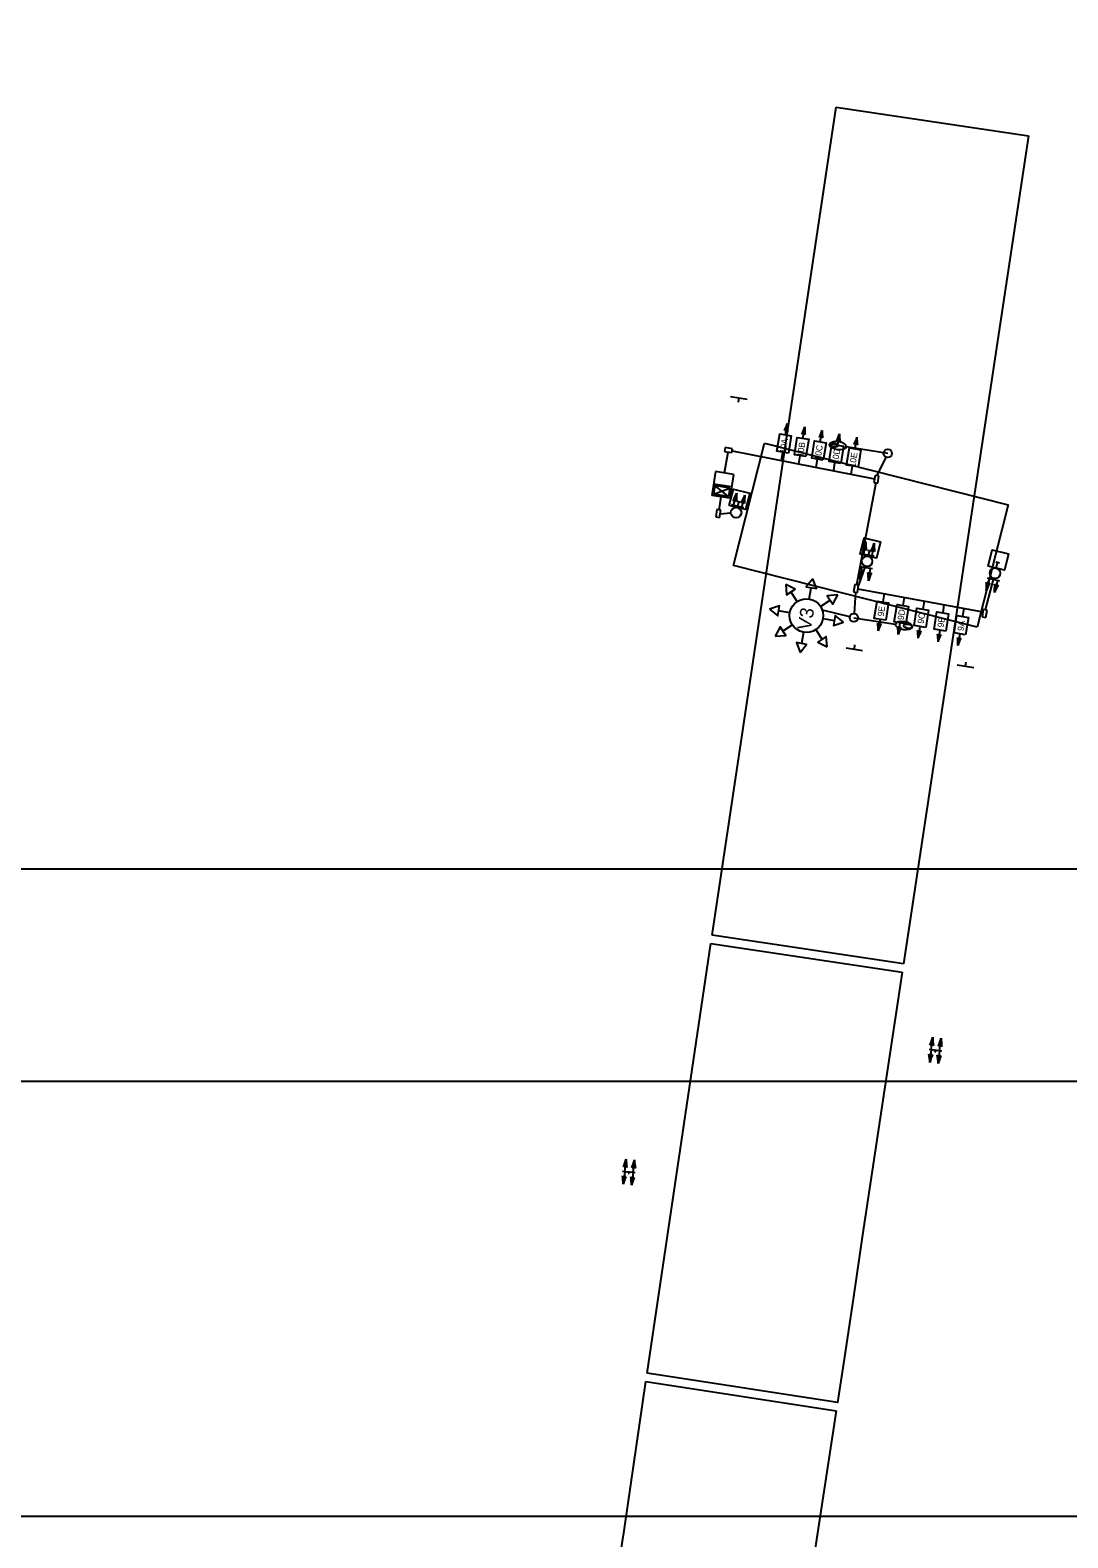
# Model space of a CAD drawing. Extents: x 991933 to 997296, y 1973751 to 1976728.
# Drawn here: x 992879.1 to 993125.8, y 1975643.9 to 1976002.3 of the extents above; entities that cross this region are included whole.
import ezdxf

# ---------------------------------------------------------------- set-up
doc = ezdxf.new("R2010")
doc.units = 0
for name, color, linetype in [('DSN_DRFT_Common-Annotations', 7, 'Continuous'), ('EX_CONTOUR_MINOR', 7, 'Continuous'), ('EX_TERRAIN', 7, 'Continuous'), ('EX_TERRAIN_TRIANGLES', 7, 'Continuous'), ('Level 23', 7, 'Continuous'), ('S_CROSS_DRAIN', 7, 'Continuous'), ('S_CURB', 7, 'Continuous'), ('S_DRIVEWAY', 7, 'Continuous'), ('S_DROP_INLET', 7, 'Continuous'), ('S_PARKING', 7, 'Continuous'), ('S_PAVEMENT_CROWN', 7, 'Continuous'), ('S_SIDEWALK', 7, 'Continuous')]:
    doc.layers.add(name, color=color, linetype=linetype)

msp = doc.modelspace()

# ---------------------------------------------------------------- linework, layer by layer
at = {"layer": 'DSN_DRFT_Common-Annotations'}
for p, q in [((993025.47, 1975681.06), (993070.74, 1975674.09)), ((993070.74, 1975674.09), (993062.63, 1975621.12))]:
    msp.add_line(p, q, dxfattribs=at)
msp.add_lwpolyline([(992995.69, 1975483.29), (992995.69, 1975483.29), (992995.69, 1975483.29), (992996.07, 1975485.68), (992998.13, 1975500.54), (993000.43, 1975515.34), (993002.81, 1975530.17), (993005.1, 1975545.07), (993007.26, 1975559.93), (993009.39, 1975574.75), (993011.66, 1975589.56), (993014.03, 1975604.36), (993015.04, 1975610.86), (993016.22, 1975619.18), (993016.22, 1975619.18), (993016.22, 1975619.18), (993016.22, 1975619.18), (993016.22, 1975619.18), (993020.39, 1975646.15), (993020.39, 1975646.15), (993020.39, 1975646.15), (993025.47, 1975681.06)], dxfattribs=at)
at = {"layer": 'EX_CONTOUR_MINOR'}
for p, q in [((993046.35, 1975875.06), (993053.72, 1975904.14)), ((993053.72, 1975904.14), (993111.64, 1975889.46)), ((993111.64, 1975889.46), (993104.27, 1975860.38)), ((993104.27, 1975860.38), (993046.35, 1975875.06))]:
    msp.add_line(p, q, dxfattribs=at)
at = {"layer": 'EX_TERRAIN'}
for p, q in [((993025.77, 1975683.04), (993040.96, 1975785.2)), ((993040.96, 1975785.2), (993086.44, 1975778.39)), ((993071.04, 1975676.07), (993025.77, 1975683.04))]:
    msp.add_line(p, q, dxfattribs=at)
msp.add_lwpolyline([(993086.44, 1975778.39), (993077.02, 1975715.99), (993074.81, 1975701.23), (993072.59, 1975686.4), (993071.04, 1975676.07), (993071.04, 1975676.07)], dxfattribs=at)
at = {"layer": 'EX_TERRAIN_TRIANGLES'}
for p, q in [((993041.25, 1975787.18), (993070.72, 1975984)), ((993070.72, 1975984), (993116.44, 1975977.15)), ((993116.44, 1975977.15), (993086.74, 1975780.37)), ((993086.74, 1975780.37), (993041.25, 1975787.18))]:
    msp.add_line(p, q, dxfattribs=at)
at = {"layer": 'Level 23'}
for points in [[(992579.43, 1975649.05), (993569.43, 1975649.05), (993569.43, 1976279.05), (992579.43, 1976279.05)], [(992760.73, 1975752.49), (993420.73, 1975752.49), (993420.73, 1976172.49), (992760.73, 1976172.49)], [(992705.67, 1975382.9), (993365.67, 1975382.9), (993365.67, 1975802.9), (992705.67, 1975802.9)]]:
    msp.add_lwpolyline(points, close=True, dxfattribs=at)
at = {"layer": 'S_CROSS_DRAIN'}
for p, q in [((993045.57, 1975915.19), (993047.55, 1975914.89)), ((993045.57, 1975915.19), (993049.53, 1975914.58)), ((993047.55, 1975914.89), (993047.4, 1975913.9)), ((993075.05, 1975855.19), (993075.2, 1975856.17)), ((993073.07, 1975855.49), (993075.05, 1975855.19)), ((993073.07, 1975855.49), (993077.02, 1975854.88)), ((993101.51, 1975851.12), (993101.66, 1975852.11)), ((993099.53, 1975851.43), (993101.51, 1975851.12)), ((993099.53, 1975851.43), (993103.48, 1975850.82))]:
    msp.add_line(p, q, dxfattribs=at)
at = {"layer": 'S_CURB'}
for p, q in [((993046.34, 1975889.33), (993047.08, 1975892.26)), ((993048.28, 1975888.85), (993049.02, 1975891.78)), ((993048.76, 1975888.73), (993045.85, 1975889.46)), ((993047.25, 1975888.85), (993047.31, 1975889.09)), ((993077.31, 1975877.68), (993077.76, 1975880.66)), ((993079.78, 1975877.3), (993076.81, 1975877.75)), ((993078.26, 1975877.28), (993078.29, 1975877.53)), ((993079.29, 1975877.38), (993079.74, 1975880.36)), ((993076.36, 1975874.78), (993079.33, 1975874.34)), ((993076.85, 1975874.71), (993076.41, 1975871.72)), ((993077.88, 1975874.81), (993077.84, 1975874.56)), ((993078.83, 1975874.42), (993078.38, 1975871.43)), ((993107.14, 1975872.01), (993106.4, 1975869.08)), ((993106.66, 1975872.13), (993109.57, 1975871.4)), ((993108.17, 1975872.01), (993108.11, 1975871.76)), ((993109.08, 1975871.52), (993108.34, 1975868.59)), ((993093.33, 1975759.92), (993093.67, 1975762.92)), ((993095.31, 1975759.69), (993095.66, 1975762.69)), ((993095.81, 1975759.63), (993092.83, 1975759.97)), ((993093.33, 1975759.92), (993092.98, 1975756.92)), ((993094.17, 1975759.57), (993094.2, 1975759.82)), ((993094.17, 1975759.57), (993094.41, 1975759.54)), ((993094.44, 1975759.79), (993094.2, 1975759.82)), ((993094.44, 1975759.79), (993094.41, 1975759.54)), ((993095.31, 1975759.69), (993094.97, 1975756.69)), ((993020.44, 1975730.97), (993020.78, 1975733.97)), ((993022.42, 1975730.74), (993022.77, 1975733.74)), ((993022.92, 1975730.69), (993019.94, 1975731.03)), ((993020.44, 1975730.97), (993020.09, 1975727.97)), ((993021.28, 1975730.62), (993021.31, 1975730.87)), ((993021.28, 1975730.62), (993021.53, 1975730.6)), ((993021.55, 1975730.84), (993021.31, 1975730.87)), ((993021.55, 1975730.84), (993021.53, 1975730.6)), ((993022.42, 1975730.74), (993022.08, 1975727.74))]:
    msp.add_line(p, q, dxfattribs=at)
for centre, radius in [((993082.99, 1975901.68), 1), ((993046.94, 1975887.64), 1.25), ((993078.07, 1975876.05), 1.25), ((993108.48, 1975873.22), 1.25), ((993074.95, 1975862.64), 1)]:
    msp.add_circle(centre, radius, dxfattribs=at)
for centre, radius, start, end in [((993033.48, 1975897.95), 14.74, 329.5654, 337.3035), ((993061.75, 1975890.86), 14.74, 174.5202, 182.2583), ((993035.42, 1975897.46), 14.74, 329.5654, 337.3035), ((993063.69, 1975890.37), 14.74, 174.5202, 182.2583), ((993046.44, 1975889.71), 0.814, 44.0645, 107.7592), ((993048.38, 1975889.22), 0.814, 44.0645, 107.7592), ((993063.69, 1975885.03), 14.74, 335.0437, 342.7818), ((993092.5, 1975880.66), 14.74, 179.9984, 187.7365), ((993077.37, 1975878.06), 0.814, 49.5428, 113.2374), ((993065.66, 1975884.73), 14.74, 335.0437, 342.7818), ((993079.35, 1975877.76), 0.814, 49.5428, 113.2374), ((993094.48, 1975880.36), 14.74, 179.9984, 187.7365), ((993076.79, 1975874.33), 0.814, 229.7294, 293.4241), ((993061.67, 1975871.68), 14.74, 0.1851, 7.9232), ((993090.5, 1975867.41), 14.74, 155.2303, 162.9684), ((993078.77, 1975874.03), 0.814, 229.7294, 293.4241), ((993063.65, 1975871.38), 14.74, 0.1851, 7.9232), ((993092.47, 1975867.11), 14.74, 155.2303, 162.9684), ((993091.74, 1975870.49), 14.74, 354.5202, 2.2583), ((993120, 1975863.39), 14.74, 149.5654, 157.3035), ((993107.04, 1975871.63), 0.814, 224.0645, 287.7592), ((993093.67, 1975870), 14.74, 354.5202, 2.2583), ((993121.94, 1975862.91), 14.74, 149.5654, 157.3035), ((993108.98, 1975871.15), 0.814, 224.0645, 287.7592), ((993079.45, 1975766.78), 14.74, 337.0766, 344.8147), ((993108.4, 1975763.44), 14.74, 182.0313, 189.7695), ((993081.44, 1975766.55), 14.74, 337.0766, 344.8147), ((993110.39, 1975763.21), 14.74, 182.0313, 189.7695), ((993093.28, 1975759.53), 0.814, 231.5757, 295.2703), ((993078.25, 1975756.39), 14.74, 2.0313, 9.7695), ((993107.2, 1975753.06), 14.74, 157.0766, 164.8147), ((993093.37, 1975760.3), 0.814, 51.5757, 115.2703), ((993095.36, 1975760.07), 0.814, 51.5757, 115.2703), ((993095.27, 1975759.3), 0.814, 231.5757, 295.2703), ((993080.24, 1975756.16), 14.74, 2.0313, 9.7695), ((993109.19, 1975752.83), 14.74, 157.0766, 164.8147), ((993006.56, 1975737.83), 14.74, 337.0766, 344.8147), ((993035.51, 1975734.5), 14.74, 182.0313, 189.7695), ((993008.55, 1975737.6), 14.74, 337.0766, 344.8147), ((993037.5, 1975734.27), 14.74, 182.0313, 189.7695), ((993020.48, 1975731.36), 0.814, 51.5757, 115.2703), ((993022.47, 1975731.13), 0.814, 51.5757, 115.2703), ((993020.39, 1975730.59), 0.814, 231.5757, 295.2703), ((993005.36, 1975727.45), 14.74, 2.0313, 9.7695), ((993034.31, 1975724.11), 14.74, 157.0766, 164.8147), ((993007.35, 1975727.22), 14.74, 2.0313, 9.7695), ((993022.38, 1975730.36), 0.814, 231.5757, 295.2703), ((993036.3, 1975723.88), 14.74, 157.0766, 164.8147)]:
    msp.add_arc(centre, radius, start, end, dxfattribs=at)
at = {"layer": 'S_DRIVEWAY'}
for p, q in [((993044.34, 1975903.06), (993044.2, 1975902.15)), ((993044.2, 1975902.15), (993045.93, 1975901.88)), ((993046.07, 1975902.78), (993044.34, 1975903.06)), ((993045.93, 1975901.88), (993046.07, 1975902.78)), ((993079.96, 1975896.48), (993079.71, 1975894.75)), ((993080.87, 1975896.35), (993079.96, 1975896.48)), ((993080.62, 1975894.62), (993080.87, 1975896.35)), ((993079.71, 1975894.75), (993080.62, 1975894.62)), ((993042.38, 1975888.32), (993042.1, 1975886.59)), ((993043.29, 1975888.17), (993042.38, 1975888.32)), ((993043.01, 1975886.44), (993043.29, 1975888.17)), ((993047.99, 1975890.02), (993047.15, 1975890.23)), ((993047.25, 1975888.85), (993047.57, 1975890.13)), ((993042.1, 1975886.59), (993043.01, 1975886.44)), ((993079.12, 1975878.43), (993078.27, 1975878.64)), ((993078.37, 1975877.26), (993078.7, 1975878.54)), ((993109.54, 1975875.6), (993108.69, 1975875.81)), ((993108.79, 1975874.43), (993109.11, 1975875.71)), ((993075.14, 1975870.5), (993074.86, 1975868.77)), ((993076.05, 1975870.35), (993075.14, 1975870.5)), ((993075.77, 1975868.63), (993076.05, 1975870.35)), ((993074.86, 1975868.77), (993075.77, 1975868.63)), ((993105.69, 1975864.57), (993105.42, 1975862.84)), ((993105.42, 1975862.84), (993106.33, 1975862.69)), ((993106.6, 1975864.42), (993105.69, 1975864.57)), ((993106.33, 1975862.69), (993106.6, 1975864.42))]:
    msp.add_line(p, q, dxfattribs=at)
at = {"layer": 'S_DROP_INLET'}
for points in [[(993045.31, 1975889.34), (993046.28, 1975893.22), (993050.16, 1975892.24), (993049.19, 1975888.36)], [(993076.43, 1975877.74), (993077.41, 1975881.62), (993081.29, 1975880.65), (993080.31, 1975876.77)], [(993106.85, 1975874.92), (993107.82, 1975878.8), (993111.7, 1975877.82), (993110.73, 1975873.94)]]:
    msp.add_lwpolyline(points, close=True, dxfattribs=at)
at = {"layer": 'S_PARKING'}
for p, q in [((993046, 1975902.33), (993079.84, 1975895.62)), ((993044.17, 1975897.04), (993045.07, 1975902.01)), ((993082.55, 1975900.78), (993080.42, 1975896.42)), ((993043.28, 1975891.36), (993042.83, 1975888.24)), ((993080.17, 1975894.69), (993075.59, 1975870.43)), ((993043.15, 1975887.31), (993045.69, 1975887.53)), ((993077.65, 1975874.87), (993076.05, 1975870.35)), ((993108.17, 1975872.01), (993106.15, 1975864.49)), ((993075.32, 1975868.7), (993075.01, 1975863.64)), ((993075.91, 1975869.49), (993105.61, 1975864.05))]:
    msp.add_line(p, q, dxfattribs=at)
at = {"layer": 'S_PAVEMENT_CROWN'}
for p, q in [((993042.03, 1975897.37), (993041.14, 1975891.7)), ((993046.31, 1975896.7), (993042.03, 1975897.37)), ((993046.31, 1975896.7), (993045.42, 1975891.03)), ((993045.42, 1975891.03), (993041.14, 1975891.7)), ((993041.84, 1975894.03), (993041.52, 1975891.98)), ((993041.52, 1975891.98), (993045.47, 1975893.46)), ((993045.15, 1975891.41), (993041.52, 1975891.98)), ((993045.85, 1975893.74), (993041.57, 1975894.41)), ((993045.47, 1975893.46), (993041.84, 1975894.03)), ((993045.12, 1975891.41), (993041.84, 1975894.03)), ((993045.47, 1975893.46), (993045.15, 1975891.41))]:
    msp.add_line(p, q, dxfattribs=at)
at = {"layer": 'S_SIDEWALK'}
for p, q in [((993058.67, 1975906.09), (993059.11, 1975908.82)), ((993062.81, 1975905.27), (993063.25, 1975908)), ((993066.95, 1975904.45), (993067.39, 1975907.18)), ((993071.09, 1975903.63), (993071.53, 1975906.36)), ((993082.99, 1975901.68), (993073.11, 1975903.23)), ((993075.23, 1975902.8), (993075.67, 1975905.54)), ((993057.71, 1975900.01), (993058.02, 1975901.97)), ((993061.85, 1975899.19), (993062.16, 1975901.15)), ((993065.99, 1975898.37), (993066.3, 1975900.33)), ((993070.13, 1975897.54), (993070.44, 1975899.51)), ((993074.26, 1975896.72), (993074.58, 1975898.69)), ((993061.45, 1975866.48), (993059.96, 1975868.75)), ((993064.34, 1975867.08), (993064.81, 1975869.76)), ((993066.99, 1975865.34), (993069.26, 1975866.84)), ((993082.13, 1975868.35), (993081.81, 1975866.38)), ((993086.87, 1975867.48), (993086.56, 1975865.51)), ((993091.62, 1975866.61), (993091.3, 1975864.64)), ((993059.72, 1975863.83), (993057.04, 1975864.3)), ((993073.98, 1975862.87), (993067.45, 1975864.42)), ((993096.36, 1975865.74), (993096.05, 1975863.77)), ((993101.11, 1975864.87), (993100.79, 1975862.91)), ((993060.32, 1975860.94), (993058.05, 1975859.44)), ((993062.97, 1975859.2), (993062.5, 1975856.52)), ((993065.86, 1975859.8), (993067.35, 1975857.53)), ((993067.6, 1975862.45), (993070.27, 1975861.99)), ((993074.95, 1975862.64), (993084.83, 1975861.09)), ((993081.15, 1975862.27), (993080.71, 1975859.54)), ((993085.89, 1975861.4), (993085.45, 1975858.67)), ((993090.64, 1975860.53), (993090.2, 1975857.8)), ((993095.38, 1975859.66), (993094.94, 1975856.93)), ((993100.13, 1975858.79), (993099.69, 1975856.06))]:
    msp.add_line(p, q, dxfattribs=at)
for points in [[(993059.39, 1975901.75), (993056.65, 1975902.2), (993057.31, 1975906.31), (993060.05, 1975905.87)], [(993063.53, 1975900.93), (993060.78, 1975901.37), (993061.45, 1975905.49), (993064.19, 1975905.05)], [(993067.67, 1975900.11), (993064.92, 1975900.55), (993065.59, 1975904.67), (993068.33, 1975904.23)], [(993071.81, 1975899.29), (993069.06, 1975899.73), (993069.72, 1975903.85), (993072.47, 1975903.4)], [(993075.95, 1975898.47), (993073.2, 1975898.91), (993073.86, 1975903.02), (993076.61, 1975902.58)], [(993058.75, 1975870.57), (993058.94, 1975868.08), (993060.97, 1975869.42)], [(993065.19, 1975871.91), (993063.61, 1975869.97), (993066.01, 1975869.55)], [(993071.09, 1975868.04), (993068.59, 1975867.86), (993069.94, 1975865.82)], [(993082.52, 1975862.05), (993079.78, 1975862.49), (993080.44, 1975866.6), (993083.18, 1975866.16)], [(993054.89, 1975864.67), (993056.83, 1975863.1), (993057.25, 1975865.5)], [(993072.43, 1975861.61), (993070.48, 1975863.19), (993070.07, 1975860.79)], [(993087.27, 1975861.18), (993084.52, 1975861.62), (993085.19, 1975865.74), (993087.93, 1975865.29)], [(993092.01, 1975860.31), (993089.27, 1975860.75), (993089.93, 1975864.87), (993092.67, 1975864.42)], [(993096.76, 1975859.44), (993094.01, 1975859.88), (993094.68, 1975864), (993097.42, 1975863.55)], [(993101.5, 1975858.57), (993098.76, 1975859.01), (993099.42, 1975863.13), (993102.16, 1975862.68)], [(993056.22, 1975858.24), (993058.72, 1975858.43), (993057.38, 1975860.46)], [(993062.13, 1975854.37), (993063.7, 1975856.31), (993061.3, 1975856.73)], [(993068.56, 1975855.71), (993068.37, 1975858.2), (993066.34, 1975856.86)]]:
    msp.add_lwpolyline(points, close=True, dxfattribs=at)
msp.add_circle((993063.66, 1975863.14), 4, dxfattribs=at)
for centre, radius, start, end in [((993046.26, 1975912.93), 13.5, 334.5209, 342.2591), ((993058.73, 1975906.44), 0.746, 49.0201, 112.7147), ((993072.61, 1975908.7), 13.5, 179.4757, 187.2138), ((993050.4, 1975912.11), 13.5, 334.5209, 342.2591), ((993062.87, 1975905.62), 0.746, 49.0201, 112.7147), ((993076.75, 1975907.88), 13.5, 179.4757, 187.2138), ((993054.54, 1975911.29), 13.5, 334.5209, 342.2591), ((993080.89, 1975907.05), 13.5, 179.4757, 187.2138), ((993058.67, 1975910.47), 13.5, 334.5209, 342.2591), ((993085.03, 1975906.23), 13.5, 179.4757, 187.2138), ((993067.01, 1975904.8), 0.746, 49.0201, 112.7147), ((993071.15, 1975903.98), 0.746, 49.0201, 112.7147), ((993062.81, 1975909.65), 13.5, 334.5209, 342.2591), ((993075.29, 1975903.15), 0.746, 49.0201, 112.7147), ((993089.17, 1975905.41), 13.5, 179.4757, 187.2138), ((993081.09, 1975861.92), 0.746, 229.02, 292.7147), ((993067.21, 1975859.66), 13.5, 359.4757, 7.2138), ((993093.57, 1975855.43), 13.5, 154.5209, 162.2591), ((993085.84, 1975861.05), 0.746, 229.02, 292.7147), ((993071.95, 1975858.79), 13.5, 359.4757, 7.2138), ((993098.31, 1975854.56), 13.5, 154.5209, 162.2591), ((993090.58, 1975860.18), 0.746, 229.02, 292.7147), ((993076.7, 1975857.92), 13.5, 359.4757, 7.2138), ((993103.05, 1975853.69), 13.5, 154.5209, 162.2591), ((993095.33, 1975859.31), 0.746, 229.02, 292.7147), ((993081.44, 1975857.05), 13.5, 359.4757, 7.2138), ((993107.8, 1975852.82), 13.5, 154.5209, 162.2591), ((993100.07, 1975858.44), 0.746, 229.02, 292.7147), ((993086.19, 1975856.18), 13.5, 359.4757, 7.2138), ((993112.54, 1975851.95), 13.5, 154.5209, 162.2591)]:
    msp.add_arc(centre, radius, start, end, dxfattribs=at)
for centre, major_axis in [((993071.13, 1975903.54), (-1.98, 0.31)), ((993070.14, 1975903.69), (0.988, -0.155)), ((993086.81, 1975860.78), (1.98, -0.31)), ((993087.79, 1975860.62), (-0.988, 0.155))]:
    msp.add_ellipse(centre, major_axis=major_axis, ratio=0.5, dxfattribs=at)

# ---------------------------------------------------------------- texts
for s, height, rotation, p in [('10A', 1.489, 81.068, (993058.72, 1975901.6)), ('10B', 1.489, 81.068, (993062.86, 1975900.77)), ('10C', 1.489, 81.068, (993067, 1975899.95)), ('10D', 1.489, 81.068, (993071.14, 1975899.14)), ('10E', 1.489, 81.068, (993075.27, 1975898.3)), ('V3', 3.25, 80.1027, (993064.63, 1975859.47)), ('9E', 1.489, 81.3279, (993082.01, 1975862.87)), ('9D', 1.489, 81.3279, (993086.76, 1975862.01)), ('9C', 1.489, 81.3279, (993091.5, 1975861.13)), ('9B', 1.489, 81.3279, (993096.25, 1975860.26)), ('9A', 1.489, 81.3279, (993100.99, 1975859.4))]:
    msp.add_text(s, height=height, rotation=rotation, dxfattribs=at).set_placement(p)

doc.saveas('drawing.dxf')
